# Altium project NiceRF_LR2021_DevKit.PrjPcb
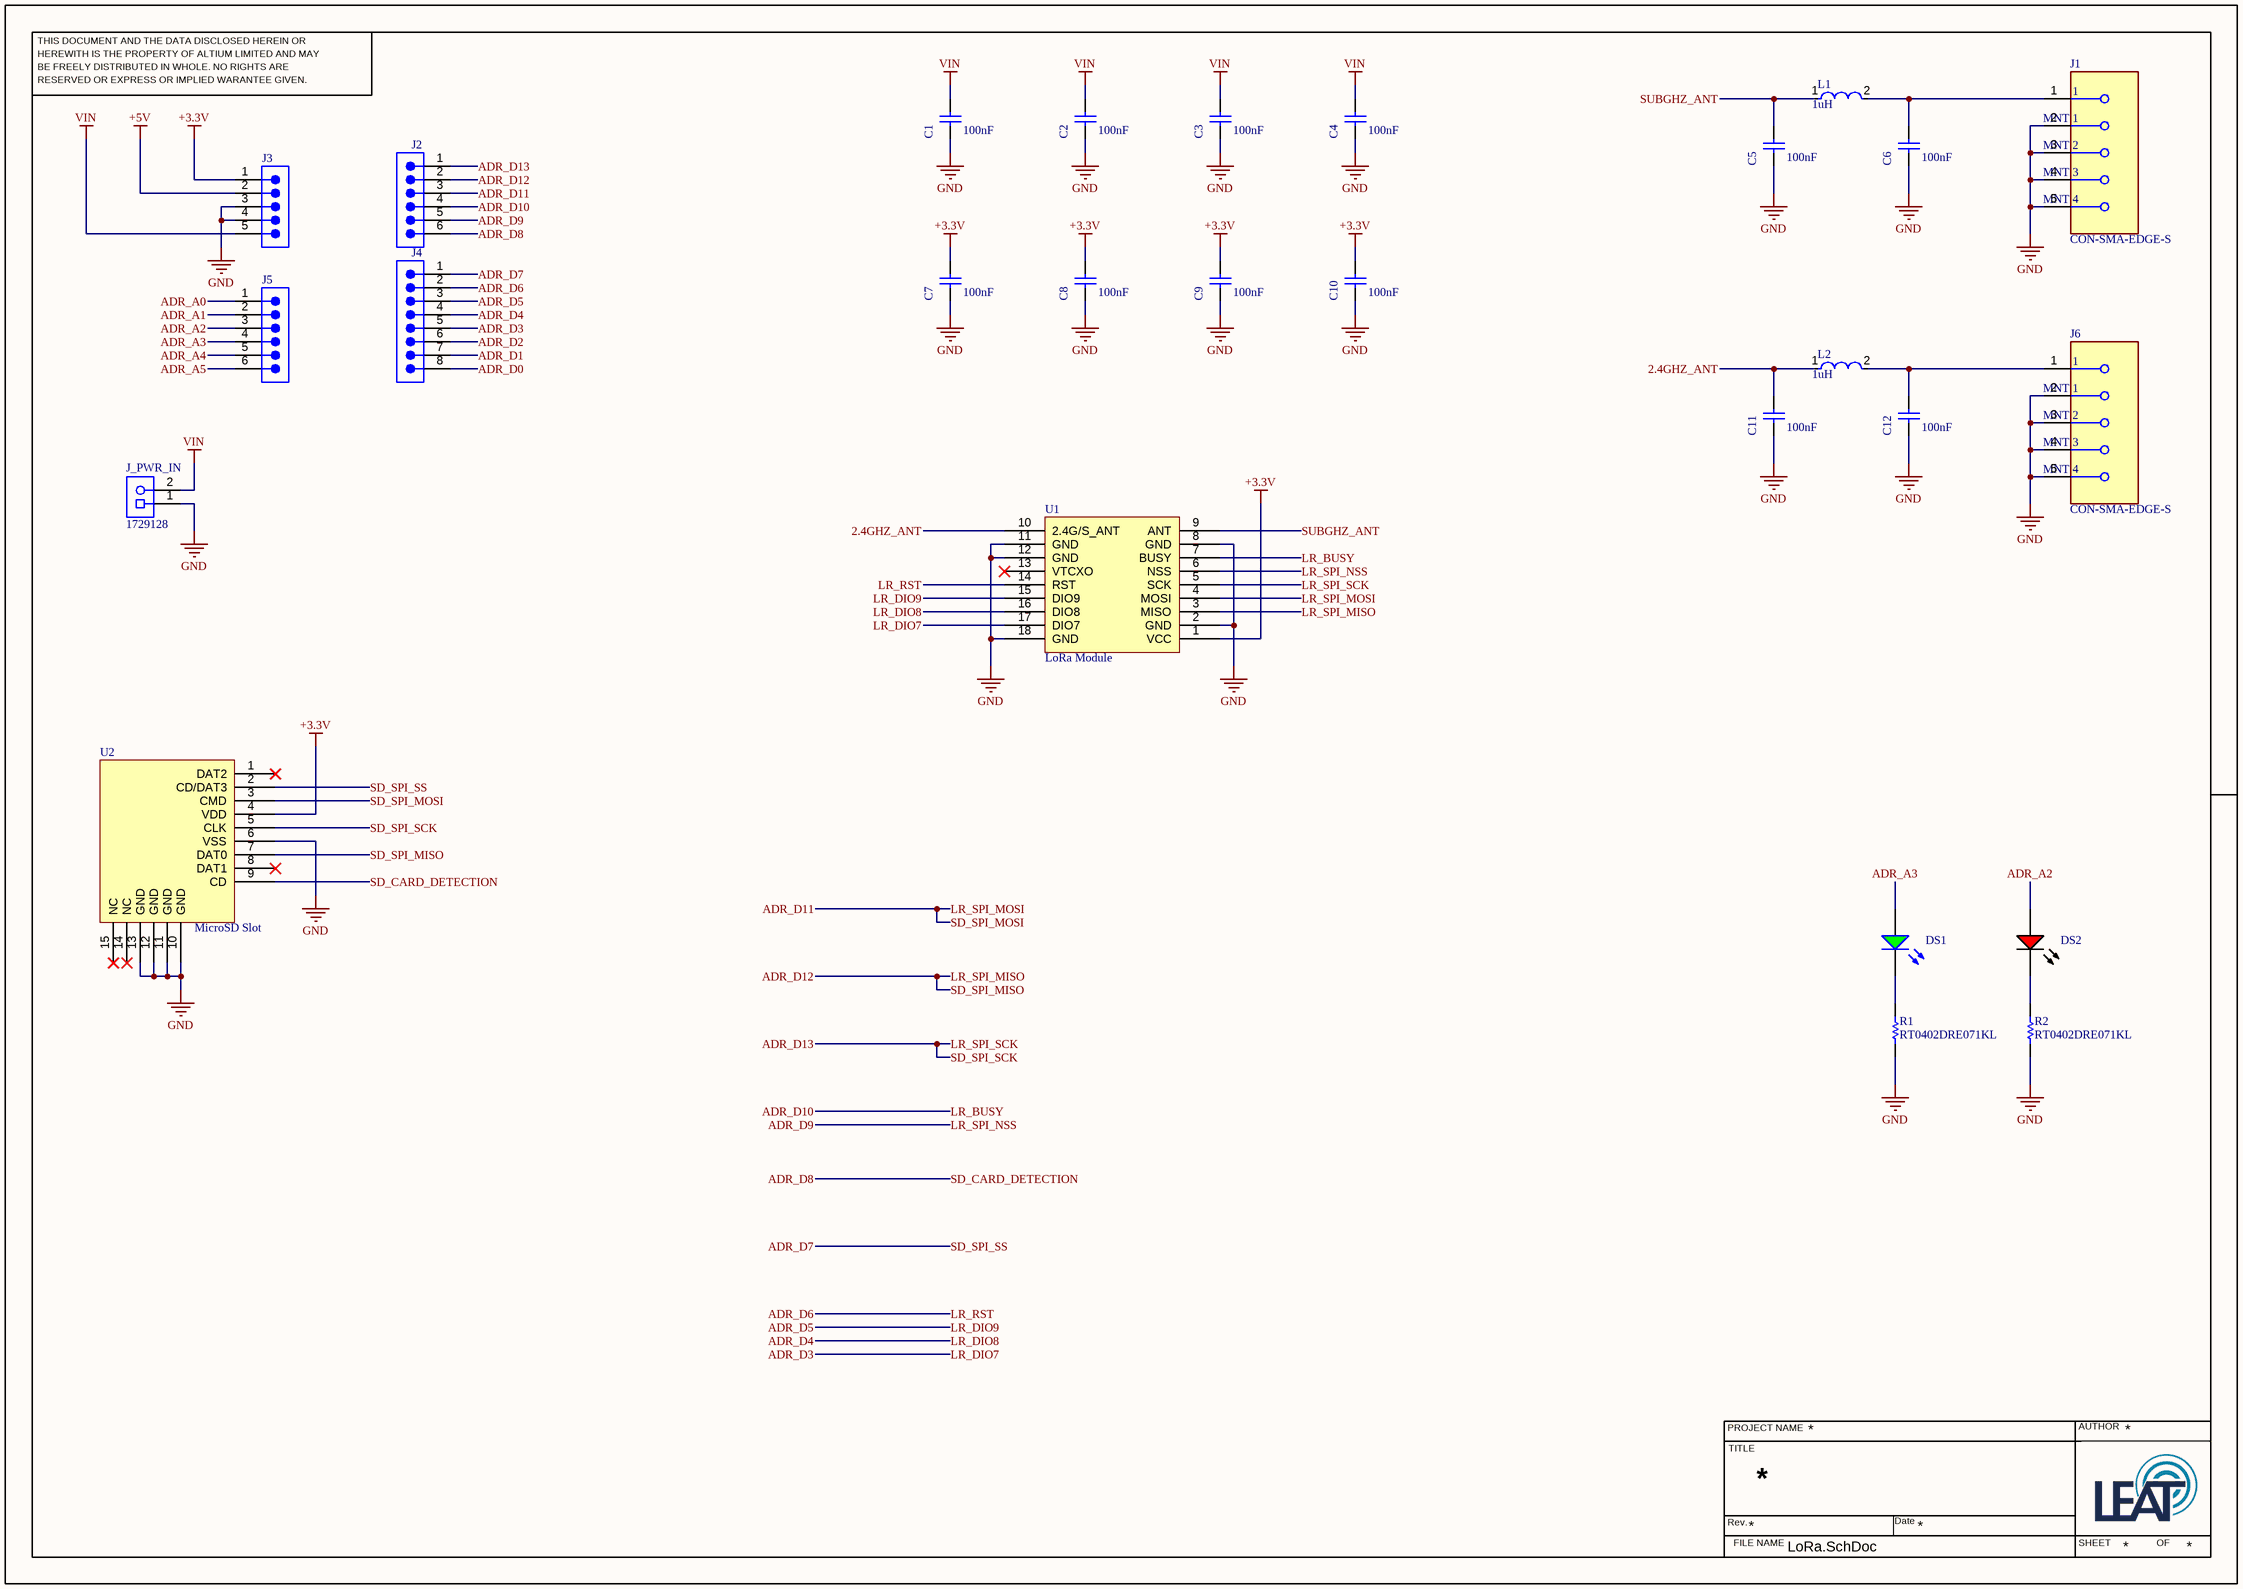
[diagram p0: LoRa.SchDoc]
1 sheet, 27 parts. Net scope: global (net labels, ports and power ports of the same name join across sheets).
Board file: PCB.PcbDoc

## Sheet LoRa.SchDoc
size 420 x 297 mm; Date: TEST

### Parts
C1  Capacitance: 100nF  [WCAP-CSGP_0402_L1W0.5H0.5]  (hidden comment: 885012205037)
C2  Capacitance: 100nF  [WCAP-CSGP_0402_L1W0.5H0.5]  (hidden comment: 885012205037)
C3  Capacitance: 100nF  [WCAP-CSGP_0402_L1W0.5H0.5]  (hidden comment: 885012205037)
C4  Capacitance: 100nF  [WCAP-CSGP_0402_L1W0.5H0.5]  (hidden comment: 885012205037)
C5  Capacitance: 100nF  [WCAP-CSGP_0402_L1W0.5H0.5]  (hidden comment: 885012205037)
C6  Capacitance: 100nF  [WCAP-CSGP_0402_L1W0.5H0.5]  (hidden comment: 885012205037)
C7  Capacitance: 100nF  [WCAP-CSGP_0402_L1W0.5H0.5]  (hidden comment: 885012205037)
C8  Capacitance: 100nF  [WCAP-CSGP_0402_L1W0.5H0.5]  (hidden comment: 885012205037)
C9  Capacitance: 100nF  [WCAP-CSGP_0402_L1W0.5H0.5]  (hidden comment: 885012205037)
C10  Capacitance: 100nF  [WCAP-CSGP_0402_L1W0.5H0.5]  (hidden comment: 885012205037)
C11  Capacitance: 100nF  [WCAP-CSGP_0402_L1W0.5H0.5]  (hidden comment: 885012205037)
C12  Capacitance: 100nF  [WCAP-CSGP_0402_L1W0.5H0.5]  (hidden comment: 885012205037)
DS1  LTST-S220GKT  [LTST-S220GKT_V]  (value not drawn)
DS2  LTST-C170KRKT  [LTST-C170KRKT_V]  (value not drawn)
J1  CON-SMA-EDGE-S  [FP-CON-SMA-EDGE-S-MFG]
J2  61300611121  [61300611121]  (value not drawn)
J3  61300511121  [61300511121]  (value not drawn)
J4  61300811121  [61300811121]  (value not drawn)
J5  61300611121  [61300611121]  (value not drawn)
J6  CON-SMA-EDGE-S  [FP-CON-SMA-EDGE-S-MFG]
J_PWR_IN  1729128  [PHOE-1729128-2_V]
L1  Inductance: 1uH  [FP-MLZ1005-MFG]  (hidden comment: MLZ1005M1R0WT000)
L2  Inductance: 1uH  [FP-MLZ1005-MFG]  (hidden comment: MLZ1005M1R0WT000)
R1  RT0402DRE071KL  [RESC1005X35X25ML10T10]
R2  RT0402DRE071KL  [RESC1005X35X25ML10T10]
U1  LoRa Module  [LR2021]
U2  MicroSD Slot  [TF-01A]

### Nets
+3.3V: C7.2 C8.2 C9.2 C10.2 J3.1 U1.1(VCC) U2.4(VDD)
+5V: J3.2
GND: C1.1 C2.1 C3.1 C4.1 C5.1 C6.1 C7.1 C8.1 C9.1 C10.1 C11.1 C12.1 J1.2(MNT_1) J1.3(MNT_2) J1.4(MNT_3) J1.5(MNT_4) J3.3 J3.4 J6.2(MNT_1) J6.3(MNT_2) J6.4(MNT_3) J6.5(MNT_4) J_PWR_IN.1 R1.1 R2.1 U1.2(GND) U1.8(GND) U1.11(GND) U1.12(GND) U1.18(GND) U2.6(VSS) U2.10(GND) U2.11(GND) U2.12(GND) U2.13(GND)
VIN: C1.2 C2.2 C3.2 C4.2 J3.5 J_PWR_IN.2
2.4GHZ_ANT: C11.2 L2.1 U1.10(2.4G/S_ANT)
ADR_A0: J5.1
ADR_A1: J5.2
ADR_A2: DS2.1(A) J5.3
ADR_A3: DS1.1(A) J5.4
ADR_A4: J5.5
ADR_A5: J5.6
ADR_D0: J4.8
ADR_D1: J4.7
ADR_D2: J4.6
ADR_D3: J4.5 U1.17(DIO7)  [also labelled LR_DIO7]
ADR_D4: J4.4 U1.16(DIO8)  [also labelled LR_DIO8]
ADR_D5: J4.3 U1.15(DIO9)  [also labelled LR_DIO9]
ADR_D6: J4.2 U1.14(RST)  [also labelled LR_RST]
ADR_D7: J4.1 U2.2(CD/DAT3)  [also labelled SD_SPI_SS]
ADR_D8: J2.6 U2.9(CD)  [also labelled SD_CARD_DETECTION]
ADR_D9: J2.5 U1.6(NSS)  [also labelled LR_SPI_NSS]
ADR_D10: J2.4 U1.7(BUSY)  [also labelled LR_BUSY]
ADR_D11: J2.3 U1.4(MOSI) U2.3(CMD)  [also labelled LR_SPI_MOSI, SD_SPI_MOSI]
ADR_D12: J2.2 U1.3(MISO) U2.7(DAT0)  [also labelled LR_SPI_MISO, SD_SPI_MISO]
ADR_D13: J2.1 U1.5(SCK) U2.5(CLK)  [also labelled LR_SPI_SCK, SD_SPI_SCK]
SUBGHZ_ANT: C5.2 L1.1 U1.9(ANT)
NetC6_2: C6.2 J1.1 L1.2
NetC12_2: C12.2 J6.1 L2.2
NetDS1_2: DS1.2(K) R1.2
NetDS2_2: DS2.2(K) R2.2

Not connected (* = marked no-connect by the designer): U1 13(VTCXO)*; U2 1(DAT2)* 8(DAT1)* 14(NC)* 15(NC)*

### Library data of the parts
C1-C12 = CMP-207839-000001-3: Cap Ceramic 0.1uF 16V X7R 10% Pad SMD 0402 125C T/R; Insulation Resistance: 5GΩ
DS1 = CMP-2000-06627-1: LED Green, 100 mW, 30 mA, -55 to 85 degC, 2-Pin SMD, RoHS, Tape and Reel; Manufacturer: Lite-On; Product Height (mm): 1mm; Number of  Elements: 1; Viewing Angle: 130deg; Test Current (It): 20mA; Reverse Voltage: 5V; Emitting Color: YellowGreen; High Brightness: No; Type: Uni-Color; Forward Current: 30mA; Peak Wavelength: 565nm; Shape Type: Rectangular; Main Category: ChipLED; Luminous Intensity: 20mcd; Power Dissipation: 100W; DELETED: Compliant; Product Depth (mm): 0.6mm; Forward Voltage: 2.6V; Dominant Wave Length: 569nm; Product Length (mm): 2.1mm
DS2 = CMP-2000-07593-1: LED Red, 75 mW, 54 mcd, -55 to 85 degC, 2-Pin SMD, RoHS, Tape and Reel; Manufacturer: Lite-On; Lens Transparency: Clear; Number of Elements: 1; Power Rating: 75mW; Luminous Intensity: 54mcd; Viewing Angle: 130degrees; Forward Current: 30mA; Wavelength: 639nm; Lens Style: Rectangular; Case\/Package: 0805; Test Current: 20mA; Dominant Wavelength: 631nm; Forward Voltage: 2V; Lens Colour: Colorless
J1 J6 = CMP-204357-000001-1: CONN SMA JACK STR EDGE MNT; Manufacturer: RF Solutions Ltd.; Impedance: 50Ω; Conn Orientation: Right Angle; Is Female: yes; Number Of Contacts: 1; Frequency: 18GHz; Shielding: true
J2 J5 = CMP-1502-01070-4: THT Vertical Pin Header WR-PHD, Pitch 2.54 mm, Single Row, 6 pins; Pitch: 2.54mm; Operating Supply Voltage: 250V; Connector Type: Male Pin; Gender: Male; Number of Positions: 6; Contact Resistance: 20mΩ; Current Rating: 3A
J3 = CMP-1502-01068-4: THT Vertical Pin Header WR-PHD, Pitch 2.54 mm, Single Row, 5 pins; Number of Contacts: 5; Connector Type: Male Pin; Operating Supply Voltage: 250V; Contact Resistance: 20mΩ; Gender: Male; Pitch: 2.54mm; Current Rating: 3A
J4 = CMP-1502-01076-4: THT Vertical Pin Header WR-PHD, Pitch 2.54 mm, Single Row, 8 pins; Pitch: 2.54mm; Voltage Rating: 250V; Connector Type: Male Pin; Current Rating: 3A; Contact Resistance: 20mΩ; Number of Positions: 8; Gender: Male
J_PWR_IN = CMP-2000-05815-1: PCB Terminal Block, 13.5 A, 400 V, 2-Pin THD, RoHS, Bulk; Manufacturer: Phoenix Contact; Package Version: 03/2015; No. of Rows: 1; Pitch: 5.08mm; No. of Positions: 2; Voltage Rating: 400V; Current Rating: 13500mA
L1 L2 = CMP-08253-000219-1: Shielded Multilayer Inductor 1uH ±20% 450mA 455mΩ SMD 0402; Core Material: Ferrite; Saturation Current: 100mA; Self Resonant Frequency: 170MHz; DC Resistance (DCR): 455mR; Test Frequency: 2MHz
R1 R2 = CMP-2002-02598-1: Manufacturer: Yageo
U1 = LR2021: LoRa2021: 160mW Multi-Band Wireless Communication Module
U2 = TF-01A: 1.85mm Card Slot MicroSD card (TF card) Self-bouncing SMD SD Card / Memory Card Connector ROHS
